// Mitsubishi GX Works2 project: MC-20MR-4MTS-F430-FX-B(U盘)例程   PLC: FX1S

PROGRAM MAIN
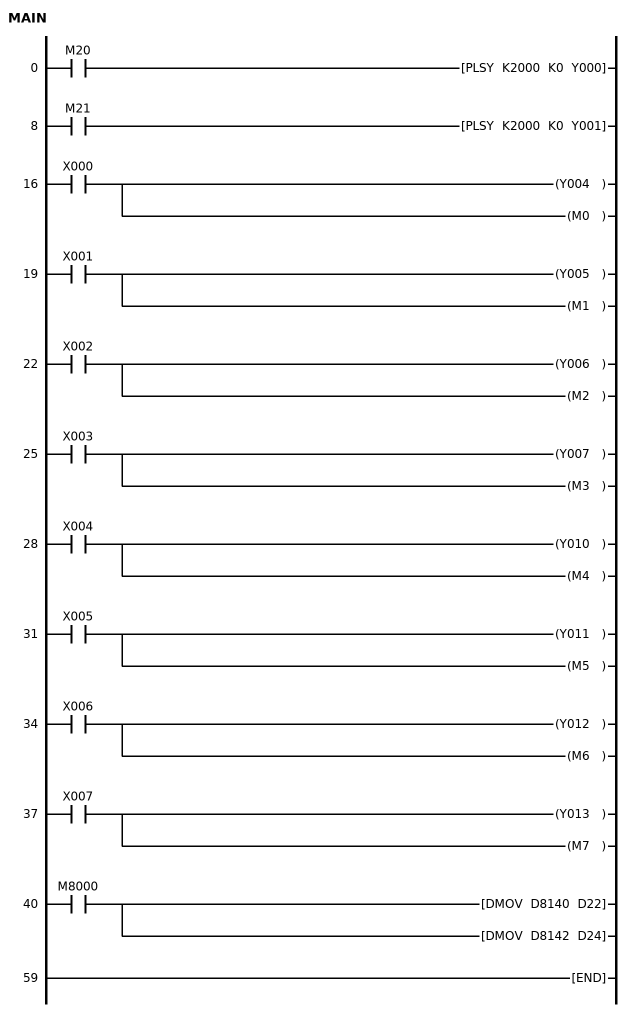
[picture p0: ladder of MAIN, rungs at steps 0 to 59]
0     LD      M20
      PLSY    K2000 K0 Y000
8     LD      M21
      PLSY    K2000 K0 Y001
16    LD      X000
      OUT     Y004
      OUT     M0
19    LD      X001
      OUT     Y005
      OUT     M1
22    LD      X002
      OUT     Y006
      OUT     M2
25    LD      X003
      OUT     Y007
      OUT     M3
28    LD      X004
      OUT     Y010
      OUT     M4
31    LD      X005
      OUT     Y011
      OUT     M5
34    LD      X006
      OUT     Y012
      OUT     M6
37    LD      X007
      OUT     Y013
      OUT     M7
40    LD      M8000
      DMOV    D8140 D22
      DMOV    D8142 D24
59    END
END_PROGRAM
